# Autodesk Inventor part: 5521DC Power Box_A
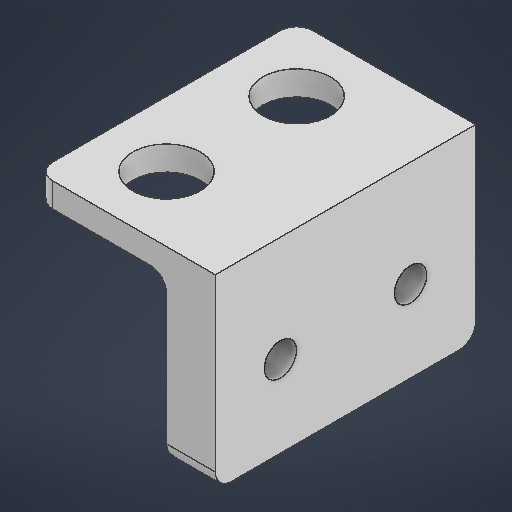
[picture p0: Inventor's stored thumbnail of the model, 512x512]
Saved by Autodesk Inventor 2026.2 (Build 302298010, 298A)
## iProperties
Created: 2026-05
Part Number: 5521DC Power Box_A
Material: 일반
Document SubType Name: Modeling
Designer: work
Density: 1 g/cm^3
Appearance: 기본값
Author: work
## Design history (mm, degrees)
sketch "스케치1"
  geometry: L1 (0, -16)-(0, 0); L2 (-8, 8)-(8, 8); L3 (8, 8)-(8, -24); L4 (8, -24)-(-8, -24); L5 (-8, -24)-(-8, 8); L6 (-8, 8)-(8, -24); L7 (8, 8)-(-8, -24); L8 (-8, 8)-(-14, 8); L9 (-14, 8)-(-14, -24); L10 (-14, -24)-(-8, -24); L11 (-8, -24)-(-8, 8); C1 r 4.15 at (0, 0); C2 r 4.15 at (0, -16); 2 further points
  constraints: 22 end point, 4 parallel, 3 midpoint, 2 centre point, 2 horizontal, 2 perpendicular, 1 coincident, 1 point on line, 1 vertical
  dimensions: "d0" = 8.3 diameter of C1; "d1" = 8.3 diameter of C2; "d2" = 16 distance of L1.start L1.end; "d3" = 8 distance from line of L3 L1.start; "d4" = 8 distance from line of L4 L1.start; "d5" = 6 distance of L9.end L10.end
extrude "돌출1" new body sketch "스케치1" distance "d6" = 3; taper "d7" = 0 deg
extrude "돌출2" join sketch "스케치1" distance "d8" = 3; taper "d10" = 0 deg; dims "d9" = 20, "d11" = 0
sketch "스케치2"
  geometry: L1 (32, 0)-(0, 0) reference; L2 (0, 0)-(0, -20) reference; L3 (32, -20)-(0, -20) reference; L4 (32, -20)-(32, 0) reference; L5 (16, 0)-(16, -20); L6 (0, -10)-(32, -10); 3 further points
  constraints: 4 end point, 4 midpoint, 1 point on line, 1 symmetric about line
  dimensions: "d13" = 16 distance of point (24, -10) point (8, -10)
hole "구멍1" sketch "스케치2" at (8, -10), (24, -10) diameter "d14" = 4; stored, may be unused: countersink angle "d18" = 90 deg, drill point angle "d20" = 118 deg; dims "d15" = 6, "d16" = 6.2, "d17" = 3, "d19" = 8
fillet "모깎기1" dims "d21" = 2
fillet "모깎기2" dims "d22" = 2
node "솔리드1"
node "투영된 루프1"
feature "A9D066F2-1C7D-4E18-AEED-F7BC21143FA4" dims "d14" = 4, "d15" = 6, "d16" = 6.2, "d17" = 3, "d18" = 90 deg, "d19" = 8, "d20" = 118 deg
